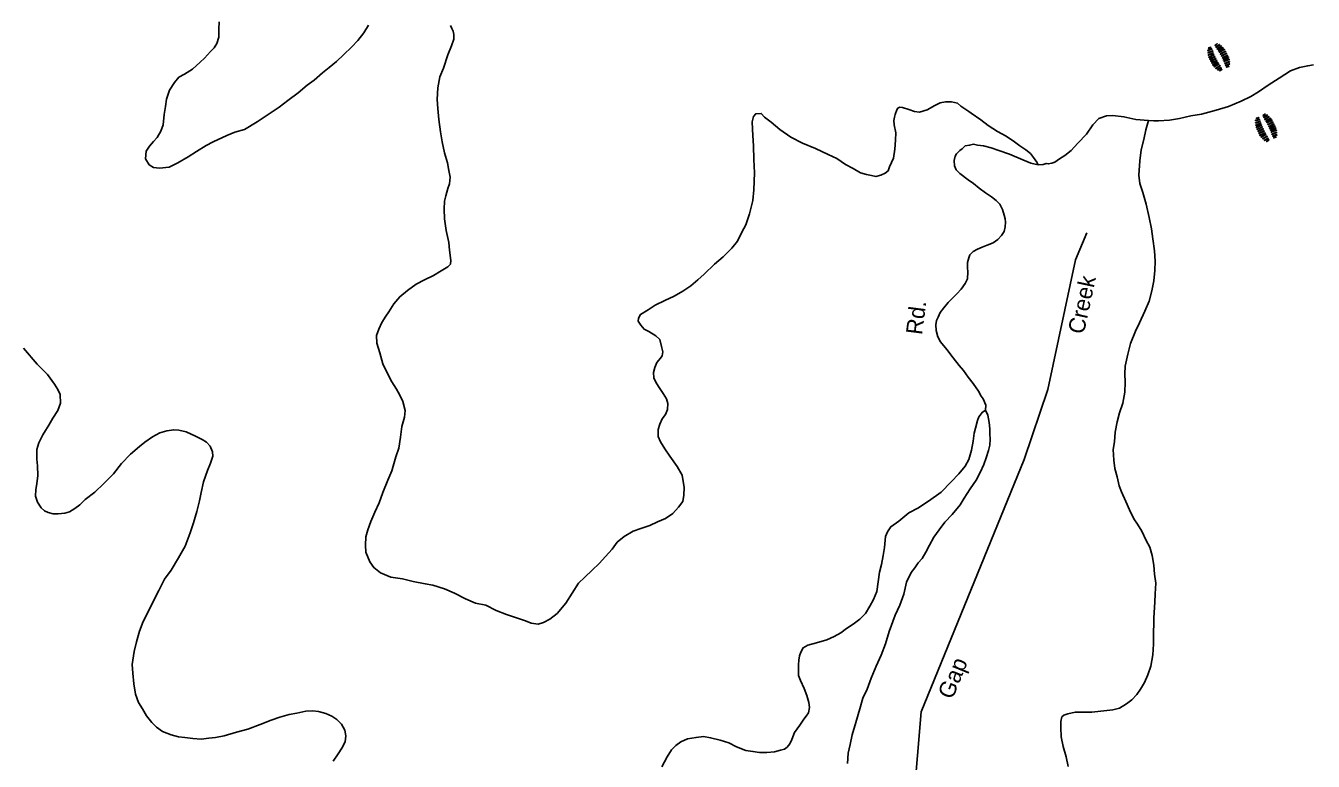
# Model space of a CAD drawing. Extents: x 884530 to 1028605, y 526725 to 653634.
# Drawn here: x 900773 to 905927, y 616365 to 619308 of the extents above; entities that cross this region are included whole.
import ezdxf

# ---------------------------------------------------------------- set-up
doc = ezdxf.new("R2010")
doc.units = 0
for name, color, linetype in [('Exist Geographical Mountain Gap CELL', 7, 'Continuous'), ('Exist Hydrographic Creek Single Shore', 7, 'Continuous'), ('Exist Hydrographic Creek Single Shore Label', 7, 'Continuous'), ('Exist Road Non-System Type 51', 7, 'Continuous'), ('Exist Road Secondary Type 51 Label', 7, 'Continuous'), ('Exist Road State Agency Type 41 National Forest', 7, 'Continuous')]:
    doc.layers.add(name, color=color, linetype=linetype)

msp = doc.modelspace()

# ---------------------------------------------------------------- linework, layer by layer
at = {"layer": 'Exist Geographical Mountain Gap CELL'}
for points in [[(905505.4, 619210.4), (905504.8, 619210.1), (905505.5, 619208.5), (905520.5, 619214), (905521.1, 619214.3), (905520.4, 619215.8)], [(905525, 619206.4), (905524.3, 619208), (905505.3, 619200.5), (905506.1, 619199)], [(905527.6, 619198), (905526.8, 619199.6), (905506.3, 619191.4), (905507.1, 619189.8)], [(905518.1, 619220.5), (905517.3, 619222), (905507.8, 619219.1), (905508.6, 619217.6)], [(905533.9, 619230), (905534.7, 619228.5), (905538.8, 619231.9), (905542.8, 619235.3), (905542, 619236.9), (905538, 619233.4)], [(905551.2, 619231.1), (905551.9, 619231.4), (905551.1, 619233), (905537.9, 619224.1), (905537.2, 619223.7), (905538, 619222.2)], [(905541.2, 619216.1), (905542, 619214.6), (905559.2, 619225.5), (905558.4, 619227.1)], [(905546.6, 619209), (905547.4, 619207.5), (905566.1, 619219.2), (905565.3, 619220.8)], [(905550.4, 619203.2), (905551.2, 619201.7), (905571.6, 619212.4), (905570.8, 619213.9)], [(905554.5, 619195.4), (905555.3, 619193.9), (905575.7, 619204.6), (905574.9, 619206.1)], [(905530.1, 619191.4), (905529.3, 619193), (905508.7, 619182.7), (905509.4, 619181.2)], [(905533.9, 619183.7), (905533.1, 619185.2), (905512.5, 619175), (905513.3, 619173.5)], [(905537.8, 619175.8), (905537, 619177.3), (905516.4, 619167.1), (905517.2, 619165.6)], [(905541.6, 619168), (905540.9, 619169.6), (905520.2, 619159.4), (905521, 619157.8)], [(905545.5, 619160.2), (905544.8, 619161.7), (905524.1, 619151.5), (905524.9, 619149.9)], [(905549.2, 619154.3), (905548.5, 619155.8), (905529.5, 619144.5), (905530.3, 619143)], [(905554.4, 619147.1), (905553.7, 619148.6), (905536.2, 619138.1), (905537, 619136.5)], [(905558.5, 619187.8), (905559.3, 619186.3), (905579.7, 619197), (905578.9, 619198.5)], [(905562.6, 619180), (905563.4, 619178.5), (905583.8, 619189.2), (905583, 619190.7)], [(905566.6, 619172.4), (905567.4, 619170.8), (905587.8, 619181.5), (905587, 619183.1)], [(905569.3, 619165.8), (905570.1, 619164.3), (905590.4, 619172.9), (905589.6, 619174.5)], [(905572, 619157.4), (905572.8, 619155.9), (905591.6, 619163.8), (905590.8, 619165.3)], [(905591.7, 619154), (905592.4, 619154.3), (905591.6, 619155.8), (905576.7, 619150), (905576.1, 619149.7), (905576.9, 619148.2)], [(905544, 619132.3), (905543.4, 619132), (905544.2, 619130.4), (905557.6, 619139), (905558.2, 619139.3), (905557.5, 619140.9)], [(905561.4, 619133), (905560.6, 619134.5), (905556.5, 619131.2), (905552.3, 619127.9), (905553.1, 619126.3), (905557.3, 619129.7)], [(905579.3, 619143.6), (905580.1, 619142), (905589.5, 619145.2), (905588.7, 619146.7)], [(905725.2, 618948.5), (905726, 618946.9), (905730.1, 618950.2), (905734.3, 618953.5), (905733.5, 618955.1), (905729.3, 618951.8)], [(905742.5, 618949), (905743.2, 618949.3), (905742.4, 618950.9), (905728.9, 618942.5), (905728.3, 618942.1), (905729, 618940.6)], [(905732, 618934.4), (905732.8, 618932.8), (905750.3, 618943.2), (905749.6, 618944.8)], [(905696.1, 618929.8), (905695.4, 618929.5), (905696.1, 618928), (905711.2, 618933), (905711.9, 618933.3), (905711.2, 618934.8)], [(905715.5, 618925.3), (905714.8, 618926.8), (905695.6, 618920), (905696.4, 618918.4)], [(905717.8, 618916.8), (905717.1, 618918.3), (905696.3, 618910.8), (905697, 618909.2)], [(905720.1, 618910.1), (905719.4, 618911.6), (905698.4, 618902.1), (905699.1, 618900.5)], [(905709, 618939.5), (905708.3, 618941.1), (905698.8, 618938.5), (905699.5, 618937)], [(905723.6, 618902.2), (905722.9, 618903.8), (905701.9, 618894.2), (905702.7, 618892.7)], [(905727.3, 618894.2), (905726.6, 618895.8), (905705.6, 618886.2), (905706.3, 618884.7)], [(905737.1, 618927.1), (905737.9, 618925.6), (905757, 618936.7), (905756.2, 618938.2)], [(905740.8, 618921.2), (905741.6, 618919.6), (905762.3, 618929.6), (905761.5, 618931.2)], [(905744.6, 618913.3), (905745.4, 618911.7), (905766.1, 618921.7), (905765.4, 618923.3)], [(905748.4, 618905.5), (905749.1, 618903.9), (905769.9, 618914), (905769.1, 618915.5)], [(905752.2, 618897.6), (905752.9, 618896), (905773.7, 618906), (905773, 618907.6)], [(905756, 618889.8), (905756.7, 618888.2), (905777.5, 618898.3), (905776.7, 618899.8)], [(905758.4, 618883.1), (905759.1, 618881.6), (905779.7, 618889.6), (905779, 618891.2)], [(905730.8, 618886.3), (905730.1, 618887.9), (905709.1, 618878.4), (905709.9, 618876.8)], [(905734.5, 618878.3), (905733.8, 618879.9), (905712.8, 618870.4), (905713.5, 618868.8)], [(905738, 618872.3), (905737.3, 618873.9), (905717.9, 618863.2), (905718.6, 618861.7)], [(905742.9, 618864.9), (905742.2, 618866.5), (905724.4, 618856.5), (905725.2, 618855)], [(905732.1, 618850.5), (905731.4, 618850.2), (905732.1, 618848.6), (905745.8, 618856.8), (905746.5, 618857.1), (905745.8, 618858.6)], [(905749.4, 618850.6), (905748.7, 618852.2), (905744.5, 618849), (905740.2, 618845.8), (905740.9, 618844.3), (905745.2, 618847.5)], [(905760.9, 618874.7), (905761.6, 618873.2), (905780.6, 618880.5), (905779.9, 618882)], [(905780.4, 618870.6), (905781.1, 618870.9), (905780.3, 618872.5), (905765.3, 618867.1), (905764.7, 618866.8), (905765.4, 618865.3)], [(905767.7, 618860.6), (905768.4, 618859.1), (905777.9, 618861.9), (905777.2, 618863.4)]]:
    msp.add_lwpolyline(points, close=True, dxfattribs=at)
at = {"layer": 'Exist Hydrographic Creek Single Shore'}
msp.add_lwpolyline([(902911.8, 614462.4), (903051.7, 614643.4), (903266.2, 614799.9), (903500.5, 615051.1), (903786.1, 615557.3), (903916, 615686), (904214.1, 615850.7), (904312.1, 616022.6), (904357.2, 616563.1), (904770, 617572.1), (904863.8, 617852.4), (904974.9, 618371.9), (905020.5, 618479.3)], dxfattribs=at)
at = {"layer": 'Exist Road Non-System Type 51'}
for points in [[(902145.3, 619310.1), (902126, 619280.3), (902102, 619249.3), (902077.2, 619222.2), (902046.1, 619192.6), (902017, 619164.3), (901988, 619141.3), (901960.9, 619119.5), (901928.2, 619090), (901900.2, 619070.9), (901864.2, 619040.1), (901822.9, 619009.4), (901788.2, 618982.5), (901747, 618955.8), (901700.1, 618923.9), (901648.9, 618893.5), (901610, 618882.4), (901578.2, 618868.6), (901522.9, 618843.5), (901496, 618828.3), (901457.2, 618805.4), (901422.9, 618783.8), (901382.1, 618759.7), (901347, 618742), (901309.1, 618737.5), (901285.2, 618740.6), (901267.1, 618751.5), (901252.1, 618775.4), (901255.1, 618806.8), (901267.9, 618826.3), (901285, 618844.3), (901299.1, 618861.1), (901314.1, 618885.7), (901323.1, 618911.8), (901327.2, 618952.4), (901332.1, 618985.1), (901337, 619013.9), (901349.2, 619050.4), (901368.2, 619081.5), (901386, 619102.2), (901409.2, 619114.8), (901440.1, 619133.9), (901471.2, 619162.2), (901489, 619178.9), (901512.1, 619204.7), (901527.2, 619220.1), (901538, 619237), (901546.1, 619261.7), (901546.1, 619294.5), (901547, 619323.4)], [(902454.1, 618627.9), (902463.2, 618656.6), (902469.2, 618674.9), (902472, 618702.4), (902467, 618728.7), (902462, 618759), (902450, 618799.9), (902440.1, 618843.5), (902433, 618883), (902427.1, 618933), (902423.1, 618976.4), (902420.2, 619013.2), (902422.1, 619059.1), (902431.2, 619103.5), (902445, 619138.7), (902463.2, 619192.1), (902478, 619227.3), (902487.1, 619254.7), (902486.1, 619273.1), (902484.1, 619286.2), (902478.1, 619296.9), (902473, 619308.8)], [(904826.2, 618751), (904820.1, 618761.6), (904807.1, 618780.2), (904794.9, 618796.2), (904776.2, 618811), (904752.9, 618827.3), (904731.2, 618843.5), (904697.9, 618866.4), (904663.1, 618885.5), (904626.2, 618908.6), (904596.1, 618931.5), (904557, 618958.5), (904547.9, 618965.3), (904516.2, 618985.6), (904503.3, 618997.7), (904479.1, 619003.4), (904455.2, 619003.9), (904433.1, 618999.1), (904412.2, 618989), (904382, 618971.2), (904351, 618962.6), (904331, 618964.4), (904308.2, 618972.7), (904282.1, 618981.1), (904272, 618982.6), (904264, 618978.8), (904259.9, 618971), (904253, 618952.8), (904251.1, 618942.3), (904247.9, 618929.3), (904249.2, 618910.9), (904256.1, 618879.2), (904255.2, 618850.4), (904252.2, 618813.7), (904246.2, 618778.4), (904231.1, 618743.2), (904225.2, 618727.6), (904213.8, 618718.6), (904195.9, 618709.8), (904176.2, 618704.9), (904157.9, 618709.3), (904138.2, 618712.3), (904114.1, 618719.3), (904084.9, 618737), (904055.1, 618753.3), (904020.1, 618776.3), (903985, 618792.8), (903933.9, 618817.4), (903882.2, 618838.2), (903835.1, 618862.7), (903792, 618892.5), (903757.2, 618922.1), (903730, 618942.3), (903717.2, 618957), (903695.2, 618956.1), (903686.1, 618944.5), (903681.1, 618923.6), (903682.2, 618894.7), (903682.9, 618868.4), (903686.1, 618827.7), (903688.2, 618772.5), (903690.1, 618719.9), (903687.1, 618651.8), (903684, 618608.5), (903670.1, 618555), (903656.1, 618511.9), (903639.1, 618482.1), (903622, 618445.7), (903599.1, 618418.6), (903564.9, 618383.8), (903530.2, 618354.3), (903489, 618314.4), (903464, 618291.3), (903435.3, 618267), (903404, 618246.6), (903369.1, 618226.3), (903331.1, 618208.7), (903292, 618189.8), (903265, 618171.9), (903234.1, 618152.9), (903226, 618138.6), (903225, 618125.5), (903235.2, 618109.5), (903248, 618093.5), (903267.9, 618085.2), (903295.1, 618067.6), (903311.2, 618052.9), (903318.2, 618025.2), (903323, 618002.8), (903320, 617987.1), (903314, 617978), (903298.9, 617961.2), (903290.9, 617940.4), (903285.9, 617920.8), (903287.1, 617899.8), (903296.2, 617878.6), (903311.2, 617856), (903324.9, 617836), (903337.9, 617814.8), (903343.1, 617796.3)], [(905267.1, 618928.5), (905257.2, 618892), (905248.2, 618852.8), (905237.9, 618811), (905233.1, 618767.8), (905229, 618710.1), (905233.2, 618677.2), (905244.3, 618640.2), (905258.1, 618594), (905270.2, 618541.2), (905279.1, 618495.1), (905284.9, 618455.6), (905291.1, 618406.9), (905293.9, 618366.2), (905292.2, 618328.2), (905289.1, 618287.5), (905281, 618247), (905270, 618206.5), (905252.2, 618166.2), (905231.2, 618119.4), (905215.1, 618085.6), (905195.1, 618036.1), (905184.1, 617994.3), (905174.2, 617945.9), (905173, 617915.8), (905173.9, 617881.6), (905172.2, 617842.3), (905165, 617797.8), (905151.1, 617758.7), (905142.2, 617723.4), (905134.1, 617681.6), (905131.1, 617643.6), (905126.2, 617612.2), (905128, 617570.1), (905133.2, 617535.9), (905142, 617502.9), (905150.2, 617467.3), (905159.2, 617443.5), (905176.2, 617403.8), (905190.9, 617370.7), (905208.9, 617334.9), (905222.9, 617313.6), (905240.1, 617285.7), (905258, 617248.6), (905272.9, 617222), (905282.1, 617187.7), (905288.9, 617149.5), (905291.1, 617114), (905296.3, 617077.2), (905294.1, 617035.2), (905293.1, 617001.1), (905288.9, 616939.5), (905288.1, 616917.2), (905287, 616879.2), (905287.1, 616833.2), (905284.9, 616791.3), (905276.1, 616745.5), (905264, 616710.3), (905250.9, 616680.4), (905235.9, 616653.1), (905221, 616632.4), (905200.9, 616610.5), (905179.9, 616595.2), (905151, 616577.4), (905125, 616571.3), (905089.1, 616566.8), (905041.1, 616561.2), (905005, 616561.9), (904973.2, 616561.2), (904944.2, 616555.3), (904928, 616549), (904920, 616542.6), (904917, 616524.3), (904915.9, 616500.7), (904917.1, 616462.6), (904925.1, 616424.4), (904938.1, 616382.1), (904946.2, 616343.9)], [(903343.1, 617796.3), (903342, 617772.7), (903334.1, 617753.1), (903321.2, 617735), (903311.9, 617714.2), (903304.9, 617692), (903304.1, 617664.5), (903314.1, 617643.3), (903331, 617615.4), (903351, 617586.1), (903380.1, 617544.8), (903401, 617510.3), (903409.2, 617460.2), (903408, 617430.1), (903403.2, 617403.9), (903386, 617382), (903363.2, 617356.2), (903334.2, 617337), (903302.1, 617323.3), (903271, 617308.1), (903235, 617295.7), (903203.9, 617285.8), (903169, 617264.2), (903141, 617241.2), (903120.1, 617214), (903093.9, 617184.4), (903069.1, 617156), (903040, 617129), (903011.2, 617102), (902986.1, 617077.6), (902961, 617037.4), (902934.9, 616997.2), (902900, 616955.9), (902871, 616932.9), (902846.1, 616920.2), (902824, 616914.1), (902796.2, 616917.3), (902773.1, 616927), (902741.1, 616938.1), (902697.1, 616952.1), (902656.1, 616968.7), (902615.2, 616989.2), (902573, 616997.9), (902534, 617014.5), (902489.1, 617037.7), (902449.1, 617055.5), (902402.2, 617069.6), (902372.1, 617075.5), (902324, 617084.3), (902280.9, 617094.3), (902235.1, 617101.8), (902193.1, 617118.4), (902166, 617140), (902151, 617162.6), (902134.1, 617201), (902133, 617229.9), (902135, 617262.7), (902142.1, 617291.4), (902154.9, 617324), (902170.1, 617361.7), (902188, 617399.4), (902203.2, 617439.8), (902223.2, 617489.3), (902239.1, 617527), (902255, 617583.2), (902266.2, 617618.4), (902273.9, 617661.5), (902279.1, 617704.7), (902289, 617741.3), (902292.2, 617768.8), (902283, 617804.4), (902270.1, 617829.6), (902257.1, 617853.5), (902238, 617882.8), (902219.1, 617922.5), (902202.1, 617955.7), (902190.1, 617999.2), (902179.1, 618037.5), (902177.1, 618069.1), (902186.1, 618093.8), (902199.2, 618121.1), (902214.1, 618145.8), (902225.9, 618163.9), (902247.2, 618195), (902270.1, 618223.4), (902301.2, 618249), (902336.1, 618274.6), (902368.9, 618291), (902406, 618308.6), (902436, 618327.7), (902463.2, 618342.9), (902473.3, 618354.5), (902474.2, 618368.9), (902469.1, 618409.7), (902467.1, 618441.3), (902456.3, 618488.7), (902450, 618534.8), (902448.1, 618574.2), (902449.1, 618605.7), (902454.1, 618627.9)], [(900764.1, 618017.3), (900818.9, 617954.5), (900860.1, 617913), (900888.2, 617874.4), (900902.2, 617853.1), (900911, 617831.9), (900912.2, 617797.8), (900901.2, 617769.1), (900881.2, 617738), (900866.2, 617709.5), (900852, 617688.7), (900841.1, 617670.6), (900826, 617639.4), (900817, 617612), (900817.2, 617573.9), (900819.9, 617547.6), (900821.1, 617508.2), (900818.2, 617475.5), (900813.1, 617451.9), (900811.9, 617425.7), (900820.9, 617401.9), (900834.3, 617379.3), (900848.1, 617367.2), (900863.1, 617360.4), (900883, 617354.7), (900903, 617355.6), (900929, 617357.7), (900948.1, 617362.6), (900970.1, 617376.6), (900989.1, 617390.7), (901011.2, 617412.5), (901049.2, 617442), (901086.3, 617476.6), (901125.1, 617515.2), (901157.1, 617556.6), (901192, 617594), (901229, 617624.7), (901250, 617641.4), (901281, 617663.1), (901310.2, 617679.5), (901337.9, 617686.9), (901365.9, 617691.6), (901386.2, 617689.8), (901415.9, 617682.7), (901453, 617666.2), (901479, 617652.5), (901496.2, 617641.7), (901511.9, 617625.6), (901521, 617603.1), (901522, 617586)], [(903979.1, 616850.3), (904008.9, 616864.1), (904035.8, 616879.3), (904058.1, 616895.9), (904085.1, 616913.8), (904112, 616932.9), (904135.1, 616956.1), (904152.1, 616985.9), (904167.1, 617011.9), (904180.2, 617044.4), (904184.9, 617082.4), (904191, 617121.7), (904198.1, 617151.7), (904205.1, 617188.3), (904210, 617219.7), (904214.2, 617264.3), (904223.1, 617282.5), (904236, 617303.2), (904267.9, 617326.2), (904308, 617359.5), (904344.1, 617377.2), (904387, 617405.2), (904437, 617442.3), (904478.1, 617483.4), (904508, 617515.6), (904533.2, 617545.3), (904548.2, 617572.6), (904559.1, 617610.4), (904565.1, 617645.8), (904570, 617677.2), (904575, 617698.1), (904582.2, 617728.1), (904588, 617743.7), (904594.1, 617750.2), (904601.2, 617760.5), (904615.1, 617769.5)], [(901522, 617586), (901513.2, 617557.3), (901500.1, 617528.7), (901484.1, 617483.1), (901475, 617440), (901468.2, 617407.3), (901458.1, 617364.2), (901444.1, 617318.5), (901431.1, 617279.4), (901411, 617226), (901385.2, 617179.3), (901355, 617130), (901328, 617093.8), (901306.1, 617048.3), (901287, 617011.9), (901265, 616965.1), (901243.2, 616924.8), (901228, 616885.8), (901216, 616842.7), (901207, 616804.8), (901199.1, 616752.5), (901202, 616717), (901206, 616674.9), (901213.1, 616634), (901224.9, 616599.7), (901240.1, 616574.4), (901256.9, 616546.5), (901278.1, 616519.9), (901296.1, 616501.1), (901321, 616483.6), (901354.9, 616471.1), (901384.2, 616462.6), (901410.1, 616459.5), (901442.2, 616456.2), (901475.9, 616452.9), (901506.2, 616457.5), (901532.2, 616459.6), (901567.1, 616466.8), (901616.9, 616481.6), (901662.1, 616493.8), (901712.1, 616512.5), (901755.1, 616530), (901790.1, 616541.1), (901828, 616552.1), (901858, 616556.8), (901894.9, 616565.2), (901922.8, 616567.3), (901945.1, 616564.2), (901974.1, 616555.8), (901998.2, 616544.8), (902018.9, 616532.6), (902036.9, 616513.8), (902049.9, 616489.9), (902055, 616466.2), (902051.9, 616442.6), (902039, 616418), (902024.1, 616394.6), (902003.1, 616364.9)], [(903319.2, 616342.4), (903341, 616382.7), (903358, 616411.2), (903375, 616427.9), (903395, 616443.3), (903422.2, 616454.5), (903456.1, 616460.4), (903486, 616463.8), (903514.2, 616459.3), (903553, 616449.3), (903586.9, 616439.4), (903618.1, 616423), (903656.2, 616407.8), (903684, 616404.7), (903709.9, 616400.2), (903740, 616399.6), (903770, 616402.9), (903794, 616409), (903809.9, 616413.9), (903821.2, 616421.6), (903831, 616434.5), (903840.2, 616452.7), (903850.9, 616480.1), (903872.2, 616509.8), (903887.1, 616533.2), (903897.2, 616544.8), (903906, 616559), (903911, 616579.9), (903907.1, 616599.7), (903899.8, 616628.7), (903888.9, 616656.5), (903874.1, 616688.3), (903867, 616708.1), (903866.1, 616727.8), (903866.9, 616751.5), (903867.9, 616769.8), (903870.2, 616786.8), (903875.1, 616801.2), (903885, 616819.3), (903903.9, 616829.5), (903938.2, 616839.3), (903979.1, 616850.3)]]:
    msp.add_lwpolyline(points, dxfattribs=at)
at = {"layer": 'Exist Road State Agency Type 41 National Forest'}
for points in [[(905927.3, 619151.5), (905904.9, 619148.1), (905871.3, 619140.9), (905836.2, 619127.1)], [(905836.2, 619127.1), (905791, 619097.8), (905746.1, 619069.9), (905707.2, 619043.1), (905677, 619025.3), (905638.2, 619006.4), (905586.9, 618985.1), (905538, 618970.3), (905480, 618954.4), (905437.2, 618947.4), (905391, 618936.5), (905351.2, 618930.8), (905307.2, 618927.7), (905289.1, 618928.1), (905267.1, 618928.5), (905217, 618933.5), (905169, 618943.6), (905125.1, 618948.4), (905099.2, 618947.6), (905069.1, 618936.4), (905044, 618912), (905019, 618874.4), (904985.1, 618838.4), (904958.2, 618808.7), (904932.9, 618789.5), (904911, 618775.5), (904892, 618761.5), (904880.1, 618757.8), (904865.9, 618755.4), (904858.1, 618756.9), (904846.2, 618753.2), (904826.2, 618751), (904796.1, 618758.1), (904764.9, 618771.9), (904711.2, 618794), (904668.2, 618809.3), (904638.2, 618819.1), (904606.2, 618827.6), (904583, 618830.7), (904567.3, 618833.6), (904551.1, 618830), (904534, 618827.7), (904522, 618816.1), (904512, 618808.5), (904499.2, 618795.6), (904493.1, 618786.5), (904490.1, 618768.2), (904491, 618747.2), (904497, 618731.3), (904512.1, 618716.6), (904545, 618691), (904567.1, 618677.4), (904590, 618658.6), (904615.2, 618639.7), (904639.2, 618623.5), (904657.9, 618608.7), (904672.1, 618593.9), (904683.1, 618572.7), (904689.9, 618550.3), (904694.2, 618535.7), (904695.2, 618522.6), (904694.2, 618502.9), (904689.9, 618484.6), (904679.1, 618469.1), (904664.9, 618452.3), (904646, 618439.6), (904622.2, 618429.5), (904601, 618422.1), (904583.1, 618414.6), (904565.2, 618404.4), (904551.8, 618391.6), (904548, 618379.8), (904543, 618360.3), (904542.2, 618339.3), (904543.9, 618323.5), (904543, 618295.9), (904534.1, 618276.4), (904516.9, 618254.5), (904500.1, 618235.1), (904484.1, 618219.7), (904465, 618200.4), (904448.1, 618179.7), (904434, 618160.3), (904425.1, 618142.1), (904418.3, 618129.1), (904415.9, 618110.8), (904417.1, 618088.4), (904424.2, 618063.4), (904434.9, 618043.5), (904460.2, 618012.8), (904485.1, 617979.4), (904510.1, 617948.8), (904527.1, 617928.7), (904545.9, 617902.1), (904565.1, 617876.8), (904586.2, 617846.2), (904596.9, 617826.3), (904604.9, 617815.6), (904615.9, 617790.4), (904615.1, 617769.5)], [(904615.1, 617769.5), (904623.9, 617749.6), (904628.9, 617720.6), (904632, 617695.6), (904631.9, 617674.6), (904633.2, 617653.6), (904632, 617630), (904627, 617607.8), (904617.9, 617579.1), (904608.8, 617553), (904594.1, 617520.5), (904577, 617489.3), (904553.1, 617455.7), (904530, 617418.1), (904513, 617390.8), (904482.1, 617352.1), (904451.9, 617321.2), (904429, 617291.5), (904408.1, 617261.7), (904391, 617229.2), (904376, 617202), (904361.1, 617176), (904346, 617159.2), (904332.1, 617138.5), (904317, 617120.4), (904299.1, 617081.4), (904288, 617033.1), (904272, 616990.1), (904253.8, 616949.8), (904229.9, 616884.6), (904214.1, 616835.1), (904197.1, 616789.5), (904177.2, 616745.2), (904156.8, 616697.1), (904140.9, 616654.1), (904124.1, 616617.7), (904112.1, 616574.6), (904096.2, 616519.8), (904081.1, 616470.2), (904073.1, 616432.3), (904065.8, 616397), (904062.1, 616356.4)]]:
    msp.add_lwpolyline(points, dxfattribs=at)

# ---------------------------------------------------------------- texts
at = {"layer": 'Exist Hydrographic Creek Single Shore Label'}
for s, rotation, p in [('Creek', 77.9245, (905008.1, 618070.8)), ('Creek', 77.9245, (905008.1, 618070.8)), ('Gap', 67.7523, (904482.2, 616609.1)), ('Gap', 67.7523, (904482.2, 616609.1))]:
    msp.add_text(s, height=65.62, rotation=rotation, dxfattribs=at).set_placement(p)
at = {"layer": 'Exist Road Secondary Type 51 Label'}
msp.add_text('Rd.', height=65.62, rotation=82.7362, dxfattribs=at).set_placement((904361, 618069))

doc.saveas('drawing.dxf')
